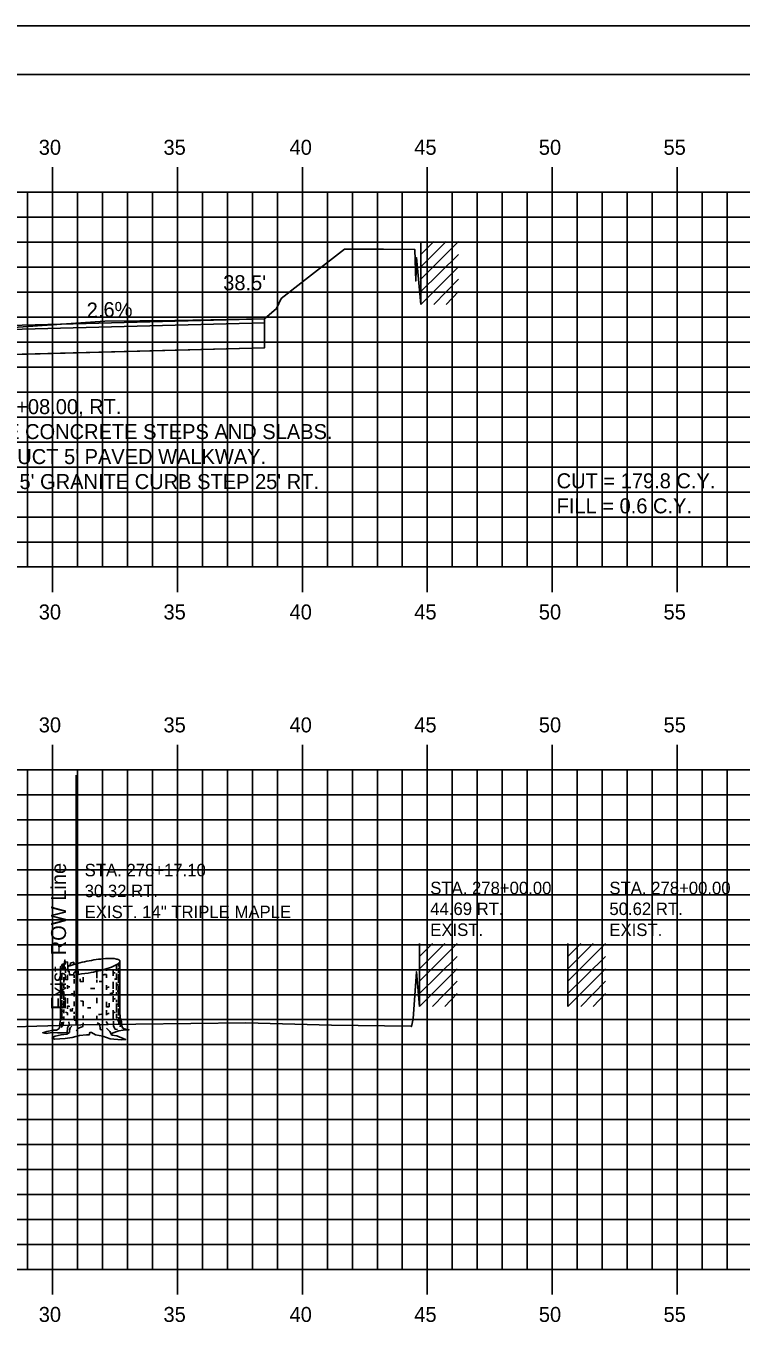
# Model space of a CAD drawing. Extents: x 854453 to 854623, y 366268 to 366378.
# Drawn here: x 854565.4 to 854594, y 366326.2 to 366378.2 of the extents above; entities that cross this region are included whole.
import ezdxf

# ---------------------------------------------------------------- set-up
doc = ezdxf.new("R2010")
doc.units = 0
for name, color, linetype in [('ANNOTATION', 7, 'Continuous'), ('BORDER', 7, 'Continuous'), ('D_Roadway_Sidewalks_Paved', 7, 'Continuous'), ('D_Roadway_SubGrade', 7, 'Continuous'), ('D_Text_Monospaced', 7, 'Continuous'), ('D_Text_Standard', 7, 'Continuous'), ('E_ROW_Line', 7, 'Continuous'), ('H_V ANNOTATION', 7, 'Continuous'), ('JUNK COM EXC', 7, 'Continuous'), ('MAJOR', 7, 'Continuous'), ('MINOR', 7, 'Continuous'), ('PLOT BOUNDARY', 7, 'Continuous'), ('S_Buildings', 7, 'Continuous'), ('S_Roadway_Centerline', 7, 'Continuous'), ('S_Trees_Decid_Pay', 7, 'Continuous')]:
    doc.layers.add(name, color=color, linetype=linetype)

msp = doc.modelspace()

# ---------------------------------------------------------------- linework, layer by layer
at = {"layer": 'BORDER'}
msp.add_line((854621.439, 366376.236), (854461.439, 366376.236), dxfattribs=at)
at = {"layer": 'D_Roadway_Sidewalks_Paved'}
for p, q in [((854561.855, 366366.118), (854574.919, 366366.457)), ((854561.855, 366365.951), (854574.919, 366366.291))]:
    msp.add_line(p, q, dxfattribs=at)
at = {"layer": 'D_Roadway_SubGrade'}
for p in [(854574.919, 366366.457), (854562.439, 366364.966)]:
    msp.add_line(p, (854574.919, 366365.29), dxfattribs=at)
at = {"layer": 'E_ROW_Line'}
msp.add_line((854567.378, 366338.192), (854567.378, 366348.192), dxfattribs=at)
at = {"layer": 'JUNK COM EXC'}
msp.add_lwpolyline([(854556.439, 366364.877), (854556.439, 366364.267), (854556.439, 366364.267), (854562.439, 366364.387), (854562.439, 366364.966), (854574.919, 366365.29), (854574.919, 366366.457), (854571.334, 366366.391), (854568.525, 366366.364), (854564.488, 366366.083), (854560.855, 366365.814), (854560.601, 366365.825), (854560.033, 366365.848), (854558.145, 366365.029), (854557.7, 366364.856), (854556.439, 366364.877)], dxfattribs=at)
at = {"layer": 'MAJOR'}
for p, q in [((854566.439, 366372.523), (854566.439, 366371.521)), ((854571.439, 366372.523), (854571.439, 366371.521)), ((854576.439, 366372.523), (854576.439, 366371.521)), ((854581.439, 366372.523), (854581.439, 366371.521)), ((854586.439, 366372.523), (854586.439, 366371.521)), ((854591.439, 366372.523), (854591.439, 366371.521)), ((854466.439, 366371.521), (854606.439, 366371.521)), ((854566.439, 366356.521), (854566.439, 366371.521)), ((854571.439, 366356.521), (854571.439, 366371.521)), ((854576.439, 366356.521), (854576.439, 366371.521)), ((854581.439, 366356.521), (854581.439, 366371.521)), ((854586.439, 366356.521), (854586.439, 366371.521)), ((854591.439, 366356.521), (854591.439, 366371.521)), ((854466.439, 366366.521), (854606.439, 366366.521)), ((854466.439, 366361.521), (854606.439, 366361.521)), ((854466.439, 366356.521), (854606.439, 366356.521)), ((854466.439, 366356.521), (854606.439, 366356.521)), ((854566.439, 366355.519), (854566.439, 366356.521)), ((854571.439, 366355.519), (854571.439, 366356.521)), ((854576.439, 366355.519), (854576.439, 366356.521)), ((854581.439, 366355.519), (854581.439, 366356.521)), ((854586.439, 366355.519), (854586.439, 366356.521)), ((854591.439, 366355.519), (854591.439, 366356.521)), ((854566.439, 366349.403), (854566.439, 366348.401)), ((854571.439, 366349.403), (854571.439, 366348.401)), ((854576.439, 366349.403), (854576.439, 366348.401)), ((854581.439, 366349.403), (854581.439, 366348.401)), ((854586.439, 366349.403), (854586.439, 366348.401)), ((854591.439, 366349.403), (854591.439, 366348.401)), ((854466.439, 366348.401), (854606.439, 366348.401)), ((854466.439, 366348.401), (854606.439, 366348.401)), ((854566.439, 366328.401), (854566.439, 366348.401)), ((854571.439, 366328.401), (854571.439, 366348.401)), ((854576.439, 366328.401), (854576.439, 366348.401)), ((854581.439, 366328.401), (854581.439, 366348.401)), ((854586.439, 366328.401), (854586.439, 366348.401)), ((854591.439, 366328.401), (854591.439, 366348.401)), ((854466.439, 366343.401), (854606.439, 366343.401)), ((854466.439, 366338.401), (854606.439, 366338.401)), ((854466.439, 366333.401), (854606.439, 366333.401)), ((854466.439, 366328.401), (854606.439, 366328.401)), ((854466.439, 366328.401), (854606.439, 366328.401)), ((854566.439, 366327.399), (854566.439, 366328.401)), ((854571.439, 366327.399), (854571.439, 366328.401)), ((854576.439, 366327.399), (854576.439, 366328.401)), ((854581.439, 366327.399), (854581.439, 366328.401)), ((854586.439, 366327.399), (854586.439, 366328.401)), ((854591.439, 366327.399), (854591.439, 366328.401))]:
    msp.add_line(p, q, dxfattribs=at)
at = {"layer": 'MINOR'}
for p, q in [((854565.439, 366356.521), (854565.439, 366371.521)), ((854567.439, 366356.521), (854567.439, 366371.521)), ((854568.439, 366356.521), (854568.439, 366371.521)), ((854569.439, 366356.521), (854569.439, 366371.521)), ((854570.439, 366356.521), (854570.439, 366371.521)), ((854572.439, 366356.521), (854572.439, 366371.521)), ((854573.439, 366356.521), (854573.439, 366371.521)), ((854574.439, 366356.521), (854574.439, 366371.521)), ((854575.439, 366356.521), (854575.439, 366371.521)), ((854577.439, 366356.521), (854577.439, 366371.521)), ((854578.439, 366356.521), (854578.439, 366371.521)), ((854579.439, 366356.521), (854579.439, 366371.521)), ((854580.439, 366356.521), (854580.439, 366371.521)), ((854582.439, 366356.521), (854582.439, 366371.521)), ((854583.439, 366356.521), (854583.439, 366371.521)), ((854584.439, 366356.521), (854584.439, 366371.521)), ((854585.439, 366356.521), (854585.439, 366371.521)), ((854587.439, 366356.521), (854587.439, 366371.521)), ((854588.439, 366356.521), (854588.439, 366371.521)), ((854589.439, 366356.521), (854589.439, 366371.521)), ((854590.439, 366356.521), (854590.439, 366371.521)), ((854592.439, 366356.521), (854592.439, 366371.521)), ((854593.439, 366356.521), (854593.439, 366371.521)), ((854466.439, 366370.521), (854606.439, 366370.521)), ((854466.439, 366369.521), (854606.439, 366369.521)), ((854466.439, 366368.521), (854606.439, 366368.521)), ((854466.439, 366367.521), (854606.439, 366367.521)), ((854466.439, 366365.521), (854606.439, 366365.521)), ((854466.439, 366364.521), (854606.439, 366364.521)), ((854466.439, 366363.521), (854606.439, 366363.521)), ((854466.439, 366362.521), (854606.439, 366362.521)), ((854466.439, 366360.521), (854606.439, 366360.521)), ((854466.439, 366359.521), (854606.439, 366359.521)), ((854466.439, 366358.521), (854606.439, 366358.521)), ((854466.439, 366357.521), (854606.439, 366357.521)), ((854565.439, 366328.401), (854565.439, 366348.401)), ((854567.439, 366328.401), (854567.439, 366348.401)), ((854568.439, 366328.401), (854568.439, 366348.401)), ((854569.439, 366328.401), (854569.439, 366348.401)), ((854570.439, 366328.401), (854570.439, 366348.401)), ((854572.439, 366328.401), (854572.439, 366348.401)), ((854573.439, 366328.401), (854573.439, 366348.401)), ((854574.439, 366328.401), (854574.439, 366348.401)), ((854575.439, 366328.401), (854575.439, 366348.401)), ((854577.439, 366328.401), (854577.439, 366348.401)), ((854578.439, 366328.401), (854578.439, 366348.401)), ((854579.439, 366328.401), (854579.439, 366348.401)), ((854580.439, 366328.401), (854580.439, 366348.401)), ((854582.439, 366328.401), (854582.439, 366348.401)), ((854583.439, 366328.401), (854583.439, 366348.401)), ((854584.439, 366328.401), (854584.439, 366348.401)), ((854585.439, 366328.401), (854585.439, 366348.401)), ((854587.439, 366328.401), (854587.439, 366348.401)), ((854588.439, 366328.401), (854588.439, 366348.401)), ((854589.439, 366328.401), (854589.439, 366348.401)), ((854590.439, 366328.401), (854590.439, 366348.401)), ((854592.439, 366328.401), (854592.439, 366348.401)), ((854593.439, 366328.401), (854593.439, 366348.401)), ((854466.439, 366347.401), (854606.439, 366347.401)), ((854466.439, 366346.401), (854606.439, 366346.401)), ((854466.439, 366345.401), (854606.439, 366345.401)), ((854466.439, 366344.401), (854606.439, 366344.401)), ((854466.439, 366342.401), (854606.439, 366342.401)), ((854466.439, 366341.401), (854606.439, 366341.401)), ((854466.439, 366340.401), (854606.439, 366340.401)), ((854466.439, 366339.401), (854606.439, 366339.401)), ((854466.439, 366337.401), (854606.439, 366337.401)), ((854466.439, 366336.401), (854606.439, 366336.401)), ((854466.439, 366335.401), (854606.439, 366335.401)), ((854466.439, 366334.401), (854606.439, 366334.401)), ((854466.439, 366332.401), (854606.439, 366332.401)), ((854466.439, 366331.401), (854606.439, 366331.401)), ((854466.439, 366330.401), (854606.439, 366330.401)), ((854466.439, 366329.401), (854606.439, 366329.401))]:
    msp.add_line(p, q, dxfattribs=at)
at = {"layer": 'PLOT BOUNDARY'}
msp.add_lwpolyline([(854453.345, 366268.177), (854623.345, 366268.177), (854623.345, 366378.177), (854453.345, 366378.177)], close=True, dxfattribs=at)
at = {"layer": 'S_Buildings'}
for p, q in [((854581.178, 366367.023), (854581.178, 366369.549)), ((854581.178, 366368.04), (854582.687, 366369.549)), ((854581.178, 366368.532), (854582.195, 366369.549)), ((854581.178, 366369.024), (854581.703, 366369.549)), ((854581.178, 366367.548), (854582.687, 366369.024)), ((854581.178, 366367.023), (854582.687, 366368.532)), ((854581.703, 366367.023), (854582.687, 366368.04)), ((854582.195, 366367.023), (854582.687, 366367.548)), ((854581.128, 366338.925), (854581.128, 366341.451)), ((854581.128, 366339.942), (854582.638, 366341.451)), ((854581.128, 366340.434), (854582.145, 366341.451)), ((854581.128, 366340.927), (854581.653, 366341.451)), ((854587.061, 366338.924), (854587.061, 366341.451)), ((854587.061, 366339.941), (854588.57, 366341.451)), ((854587.061, 366340.434), (854588.078, 366341.451)), ((854587.061, 366340.926), (854587.586, 366341.451)), ((854581.128, 366339.45), (854582.638, 366340.927)), ((854587.061, 366339.449), (854588.57, 366340.926)), ((854581.128, 366338.925), (854582.638, 366340.434)), ((854581.653, 366338.925), (854582.638, 366339.942)), ((854587.061, 366338.924), (854588.57, 366340.434)), ((854587.586, 366338.924), (854588.57, 366339.941)), ((854582.145, 366338.925), (854582.638, 366339.45)), ((854588.078, 366338.924), (854588.57, 366339.449))]:
    msp.add_line(p, q, dxfattribs=at)
at = {"layer": 'S_Roadway_Centerline'}
for points in [[(854564.488, 366366.083), (854568.525, 366366.364), (854571.334, 366366.391), (854574.919, 366366.457), (854575.406, 366366.873), (854575.586, 366367.263), (854576.808, 366368.22), (854578.128, 366369.249), (854579.68, 366369.245), (854580.939, 366369.236), (854580.973, 366367.966), (854581.007, 366368.905), (854581.178, 366367.023)], [(854563.145, 366338.061), (854567.572, 366338.198), (854574.173, 366338.276), (854577.605, 366338.183), (854580.792, 366338.137), (854580.801, 366338.123), (854580.869, 366338.44), (854581.002, 366340.319), (854581.128, 366338.926)]]:
    msp.add_lwpolyline(points, dxfattribs=at)
at = {"layer": 'S_Trees_Decid_Pay'}
for p, q in [((854566.955, 366340.446), (854566.955, 366340.272)), ((854568.999, 366340.605), (854568.999, 366340.352)), ((854569.079, 366340.649), (854569.079, 366340.529)), ((854569.079, 366340.477), (854569.079, 366340.263)), ((854566.805, 366340.246), (854566.805, 366339.991)), ((854566.891, 366340.1), (854566.891, 366339.888)), ((854567.039, 366340.197), (854567.039, 366339.993)), ((854567.3, 366340.199), (854567.3, 366340.08)), ((854567.3, 366340.028), (854567.3, 366339.843)), ((854567.539, 366339.928), (854567.544, 366340.035)), ((854567.665, 366340.1), (854567.665, 366339.92)), ((854568.211, 366340.337), (854568.211, 366340.057)), ((854568.211, 366339.991), (854568.211, 366339.888)), ((854568.594, 366340.438), (854568.594, 366340.352)), ((854568.594, 366340.211), (854568.594, 366340.071)), ((854568.867, 366340.352), (854568.867, 366340.16)), ((854568.999, 366340.255), (854568.999, 366339.991)), ((854569.079, 366340.218), (854569.079, 366339.88)), ((854566.805, 366339.894), (854566.805, 366339.425)), ((854566.891, 366339.823), (854566.891, 366339.674)), ((854566.891, 366339.497), (854566.891, 366339.197)), ((854567.039, 366339.785), (854567.039, 366339.631)), ((854567.3, 366339.557), (854567.3, 366339.329)), ((854568.594, 366339.785), (854568.594, 366339.594)), ((854568.867, 366339.909), (854568.867, 366339.631)), ((854568.867, 366339.586), (854568.867, 366339.477)), ((854568.999, 366339.894), (854568.999, 366339.586)), ((854568.999, 366339.497), (854568.999, 366339.431)), ((854569.079, 366339.763), (854569.079, 366339.402)), ((854566.805, 366339.374), (854566.805, 366339.24)), ((854566.805, 366339.182), (854566.805, 366338.857)), ((854566.891, 366339.159), (854566.891, 366338.917)), ((854567.039, 366339.268), (854567.039, 366339.048)), ((854567.039, 366338.949), (854567.039, 366338.828)), ((854567.3, 366339.13), (854567.3, 366338.945)), ((854567.665, 366339.142), (854567.665, 366338.945)), ((854568.211, 366339.277), (854568.211, 366339.056)), ((854568.594, 366339.114), (854568.594, 366338.906)), ((854568.867, 366339.342), (854568.867, 366339.114)), ((854568.999, 366339.197), (854568.999, 366339.1)), ((854568.999, 366339.048), (854568.999, 366338.688)), ((854569.079, 366339.365), (854569.079, 366338.917)), ((854566.805, 366338.828), (854566.805, 366338.408)), ((854566.891, 366338.806), (854566.891, 366338.665)), ((854566.891, 366338.533), (854566.891, 366338.377)), ((854567.039, 366338.677), (854567.039, 366338.579)), ((854567.3, 366338.711), (854567.3, 366338.634)), ((854567.3, 366338.556), (854567.3, 366338.383)), ((854567.665, 366338.562), (854567.665, 366338.459)), ((854568.211, 366338.556), (854568.211, 366338.383)), ((854568.594, 366338.785), (854568.594, 366338.585)), ((854568.867, 366338.785), (854568.867, 366338.401)), ((854568.999, 366338.636), (854568.999, 366338.47)), ((854569.079, 366338.851), (854569.079, 366338.569)), ((854566.808, 366338.305), (854566.794, 366338.188)), ((854568.59, 366338.328), (854568.67, 366338.196))]:
    msp.add_line(p, q, dxfattribs=at)
for points in [[(854566.755, 366340.52), (854566.755, 366338.383), (854566.734, 366338.241), (854566.728, 366338.115), (854566.685, 366338.029), (854566.592, 366337.98), (854566.457, 366337.98), (854566.213, 366337.924), (854566.047, 366337.875), (854566.189, 366337.844), (854566.426, 366337.881), (854566.636, 366337.869), (854566.897, 366337.875), (854567.021, 366337.893), (854567.051, 366337.85), (854567.113, 366337.893), (854567.014, 366337.825), (854566.779, 366337.8), (854566.549, 366337.739), (854566.419, 366337.669), (854566.518, 366337.625), (854566.94, 366337.644), (854567.218, 366337.688), (854567.517, 366337.764), (854567.803, 366337.8), (854567.908, 366337.8), (854567.926, 366337.881), (854567.995, 366337.887), (854568.161, 366337.8), (854568.447, 366337.745), (854568.746, 366337.638), (854569.205, 366337.588), (854569.36, 366337.601), (854569.018, 366337.751), (854568.814, 366337.782), (854568.826, 366337.856), (854569.086, 366337.955), (854569.261, 366337.986), (854569.502, 366337.998), (854569.304, 366338.035), (854569.242, 366338.072), (854569.218, 366338.159), (854569.205, 366338.328), (854569.16, 366338.414), (854569.132, 366338.655), (854569.132, 366340.741)], [(854567.111, 366340.193), (854567.103, 366340.337), (854567.058, 366340.329), (854567.043, 366340.704), (854566.949, 366340.712), (854566.934, 366340.792), (854566.897, 366340.455), (854566.852, 366340.549), (854566.831, 366340.395), (854566.755, 366340.52), (854566.76, 366340.331)], [(854566.755, 366340.52), (854566.8, 366340.543), (854566.823, 366340.609), (854566.875, 366340.632), (854566.908, 366340.557)], [(854567.133, 366340.559), (854567.154, 366340.667), (854567.286, 366340.697), (854567.293, 366340.609)], [(854567.272, 366340.197), (854567.309, 366340.3), (854567.375, 366340.306), (854567.375, 366340.388), (854567.449, 366340.395), (854567.474, 366340.214)], [(854568.708, 366338.92), (854568.707, 366338.997), (854568.699, 366339.063)], [(854567.163, 366338.828), (854567.154, 366338.754), (854567.228, 366338.748), (854567.243, 366338.865)], [(854569.024, 366338.416), (854569.096, 366338.313), (854569.096, 366338.188)], [(854569.081, 366338.497), (854569.142, 366338.336), (854569.155, 366338.211), (854569.148, 366338.113)], [(854566.875, 366338.313), (854566.868, 366338.188), (854566.786, 366338.093)], [(854567.021, 366337.893), (854567.039, 366338.072), (854567.101, 366338.209), (854567.094, 366338.309)], [(854567.212, 366338.14), (854567.138, 366338.072), (854567.119, 366337.974), (854567.113, 366337.893)], [(854567.663, 366338.276), (854567.646, 366338.122), (854567.449, 366338.041), (854567.403, 366337.938)], [(854568.229, 366338.268), (854568.332, 366338.216), (854568.346, 366338.01), (854568.449, 366337.982)], [(854568.814, 366337.782), (854568.728, 366337.924), (854568.596, 366338.066)], [(854568.884, 366338.342), (854568.884, 366338.136), (854568.942, 366338.027), (854569.039, 366338.01)]]:
    msp.add_lwpolyline(points, dxfattribs=at)
for centre, radius, start, end in [((854567.564, 366339.333), 1.299, 107.8613, 113.3069), ((854569.045, 366334.739), 6.126, 100.7779, 107.8613), ((854569.045, 366334.739), 6.126, 93.6944, 100.7779), ((854566.842, 366346.308), 6.126, 280.7779, 287.8613), ((854568.734, 366339.556), 1.299, 78.2779, 93.6944), ((854568.323, 366341.714), 1.299, 287.8613, 303.2779), ((854568.9, 366340.358), 0.48, 69.9843, 78.2779), ((854568.772, 366341.029), 0.48, 303.2779, 311.5714), ((854569.008, 366340.655), 0.164, 55.7779, 69.9843), ((854568.982, 366340.793), 0.164, 311.5714, 325.7779), ((854569.04, 366340.702), 0.107, 45.9547, 55.7779), ((854569.07, 366340.732), 0.0645, 33.2779, 45.9547), ((854569.029, 366340.761), 0.107, 325.7779, 335.6011), ((854569.078, 366340.738), 0.0544, 22.46, 33.2779), ((854569.068, 366340.743), 0.0645, 335.6011, 348.2779), ((854569.085, 366340.741), 0.0467, 10.7779, 22.46), ((854569.085, 366340.741), 0.0467, 359.0957, 10.7779), ((854569.078, 366340.741), 0.0544, 348.2779, 359.0957), ((854566.802, 366340.152), 0.0476, 180, 191.6815), ((854566.81, 366340.153), 0.0554, 191.6815, 202.5), ((854566.82, 366340.157), 0.0657, 202.5, 215.1737), ((854566.855, 366340.182), 0.109, 215.1737, 225), ((854566.896, 366340.223), 0.166, 225, 239.1924), ((854567.368, 366341.242), 1.292, 250.6119, 255.2856), ((854567.153, 366341.492), 1.299, 268.1289, 273.6944), ((854566.842, 366346.308), 6.126, 273.6944, 274.0246), ((854566.842, 366346.308), 6.126, 275.9147, 280.7779), ((854567.943, 366345.83), 5.916, 266.0776, 267.3043), ((854567.943, 366345.83), 5.916, 273.5382, 274.8924), ((854567.944, 366346.091), 5.916, 274.9515, 276.3087), ((854568.52, 366341.503), 1.292, 285.5651, 289.0916), ((854568.519, 366341.242), 1.292, 288.0829, 292.5), ((854568.828, 366340.496), 0.484, 297.4162, 300.8076), ((854568.991, 366340.223), 0.166, 300.8076, 315), ((854568.992, 366340.484), 0.166, 301.67, 315), ((854569.032, 366340.182), 0.109, 315, 324.8263), ((854569.033, 366340.443), 0.109, 315, 324.8263), ((854569.067, 366340.157), 0.0657, 324.8263, 337.5), ((854569.068, 366340.418), 0.0657, 324.8263, 337.5), ((854569.077, 366340.153), 0.0554, 337.5, 348.3185), ((854569.078, 366340.414), 0.0554, 337.5, 348.3185), ((854566.802, 366339.631), 0.0476, 180, 191.6815), ((854566.81, 366339.633), 0.0554, 191.6815, 202.5), ((854566.82, 366339.636), 0.0657, 202.5, 215.1737), ((854566.855, 366339.661), 0.109, 215.1737, 225), ((854566.896, 366339.702), 0.166, 225, 239.1924), ((854566.896, 366339.959), 0.166, 237.0378, 239.1924), ((854567.058, 366340.232), 0.484, 239.1924, 247.5), ((854567.058, 366339.975), 0.484, 239.1924, 245.7725), ((854567.368, 366340.979), 1.292, 247.5, 248.3537), ((854567.368, 366340.721), 1.292, 247.5, 248.4842), ((854567.368, 366340.979), 1.292, 255.2856, 259.2632), ((854567.368, 366340.721), 1.292, 261.8726, 262.8454), ((854567.943, 366345.309), 5.916, 262.8454, 263.7595), ((854567.943, 366345.567), 5.916, 270.1162, 271.7708), ((854567.943, 366345.567), 5.916, 276.3184, 277.1546), ((854568.519, 366340.979), 1.292, 277.1546, 278.3662), ((854568.519, 366340.721), 1.292, 279.2565, 285.6105), ((854568.519, 366340.979), 1.292, 291.8071, 292.5), ((854568.828, 366340.232), 0.484, 292.5, 300.8076), ((854568.828, 366339.975), 0.484, 294.6372, 300.8076), ((854568.991, 366339.959), 0.166, 300.8076, 301.6001), ((854568.991, 366339.702), 0.166, 300.8076, 315), ((854569.032, 366339.661), 0.109, 315, 324.8263), ((854569.067, 366339.636), 0.0657, 324.8263, 337.5), ((854569.077, 366339.633), 0.0554, 337.5, 348.3185), ((854566.802, 366339.374), 0.0476, 180, 191.6815), ((854566.802, 366339.108), 0.0476, 180, 191.6815), ((854566.81, 366339.375), 0.0554, 191.6815, 202.5), ((854566.81, 366339.11), 0.0554, 191.6815, 202.5), ((854566.82, 366339.379), 0.0657, 202.5, 215.1737), ((854566.82, 366339.113), 0.0657, 202.5, 215.1737), ((854566.855, 366339.404), 0.109, 215.1737, 225), ((854566.855, 366339.138), 0.109, 215.1737, 225), ((854566.896, 366339.445), 0.166, 225, 239.1924), ((854566.896, 366339.179), 0.166, 225, 239.1924), ((854567.058, 366339.452), 0.484, 239.1924, 247.5), ((854567.368, 366340.464), 1.292, 247.5, 251.799), ((854567.368, 366340.198), 1.292, 247.5, 248.3537), ((854567.368, 366340.198), 1.292, 255.2856, 259.2463), ((854567.943, 366345.052), 5.916, 266.2721, 267.3043), ((854567.943, 366344.786), 5.916, 276.3184, 277.1546), ((854568.519, 366340.198), 1.292, 277.1546, 278.3795), ((854568.519, 366340.464), 1.292, 285.6105, 290.1001), ((854568.828, 366339.452), 0.484, 292.5, 300.8076), ((854568.991, 366339.179), 0.166, 300.8076, 302.0694), ((854568.991, 366339.445), 0.166, 302.0694, 315), ((854569.032, 366339.404), 0.109, 315, 324.8263), ((854569.067, 366339.379), 0.0657, 324.8263, 337.5), ((854569.077, 366339.375), 0.0554, 337.5, 348.3185), ((854569.077, 366339.11), 0.0554, 337.5, 348.3185), ((854566.802, 366338.579), 0.0476, 180, 191.6815), ((854566.81, 366338.58), 0.0554, 191.6815, 202.5), ((854566.82, 366338.584), 0.0657, 202.5, 215.1737), ((854566.855, 366338.609), 0.109, 215.1737, 225), ((854566.896, 366338.65), 0.166, 225, 239.1924), ((854567.058, 366338.923), 0.484, 239.1924, 247.5), ((854567.058, 366339.18), 0.484, 242.734, 247.5), ((854567.368, 366339.669), 1.292, 247.5, 248.3537), ((854567.368, 366339.927), 1.292, 251.3664, 255.2856), ((854567.943, 366344.257), 5.916, 263.7831, 264.7656), ((854567.943, 366344.786), 5.916, 268.9207, 270), ((854567.943, 366344.786), 5.916, 270, 270.2757), ((854567.943, 366344.514), 5.916, 273.2637, 274.461), ((854567.943, 366344.514), 5.916, 276.3184, 277.1546), ((854568.519, 366339.927), 1.292, 277.1546, 278.3662), ((854568.519, 366339.927), 1.292, 285.6105, 289.1534), ((854568.528, 366339.673), 1.292, 291.3696, 292.0604), ((854568.828, 366338.923), 0.484, 292.5, 296.5499), ((854568.991, 366338.907), 0.166, 302.0694, 315), ((854569.032, 366338.867), 0.109, 315, 324.8263), ((854569.067, 366338.842), 0.0657, 324.8263, 337.5), ((854569.077, 366338.838), 0.0554, 337.5, 348.3185)]:
    msp.add_arc(centre, radius, start, end, dxfattribs=at)

# ---------------------------------------------------------------- texts
at = {"layer": 'ANNOTATION'}
msp.add_text('2.6%', height=0.6, rotation=1.4887, dxfattribs=at).set_placement((854567.815, 366366.501))
for s, p in [('STA. 278+08.00, RT.', (854561.639, 366362.641)), ('REMOVE CONCRETE STEPS AND SLABS.', (854561.639, 366361.641)), ("CONSTRUCT 5' PAVED WALKWAY.", (854561.639, 366360.641)), ("INSTALL 5' GRANITE CURB STEP 25' RT.", (854561.639, 366359.641)), ('CUT = 179.8 C.Y.', (854586.615, 366359.671)), ('FILL = 0.6 C.Y.', (854586.615, 366358.669))]:
    msp.add_text(s, height=0.6, dxfattribs=at).set_placement(p)
at = {"layer": 'D_Text_Monospaced'}
for s, height, p in [('STA. 278+17.10', 0.49998, (854567.724, 366344.139)), ('30.32 RT.', 0.5, (854567.724, 366343.305)), ('STA. 278+00.00', 0.49998, (854581.556, 366343.424)), ('STA. 278+00.00', 0.49998, (854588.727, 366343.423)), ('44.69 RT.', 0.5, (854581.556, 366342.59)), ('50.62 RT.', 0.5, (854588.727, 366342.589)), ('EXIST. 14" TRIPLE MAPLE', 0.49998, (854567.724, 366342.465)), ('EXIST. ', 0.5, (854581.556, 366341.75)), ('EXIST. ', 0.5, (854588.727, 366341.749))]:
    msp.add_text(s, height=height, dxfattribs=at).set_placement(p)
at = {"layer": 'D_Text_Standard'}
msp.add_text("38.5'", height=0.6, dxfattribs=at).set_placement((854573.27, 366367.601))
at = {"layer": 'E_ROW_Line'}
msp.add_text('Exist. ROW Line', height=0.6, rotation=90, dxfattribs=at).set_placement((854566.978, 366338.792))
at = {"layer": 'H_V ANNOTATION'}
for s, p in [('30', (854565.887, 366373.021)), ('35', (854570.879, 366373.021)), ('40', (854575.925, 366373.021)), ('45', (854580.917, 366373.021)), ('50', (854585.903, 366373.021)), ('55', (854590.895, 366373.021)), ('30', (854565.887, 366354.421)), ('35', (854570.879, 366354.421)), ('40', (854575.925, 366354.421)), ('45', (854580.917, 366354.421)), ('50', (854585.903, 366354.421)), ('55', (854590.895, 366354.421)), ('30', (854565.887, 366349.901)), ('35', (854570.879, 366349.901)), ('40', (854575.925, 366349.901)), ('45', (854580.917, 366349.901)), ('50', (854585.903, 366349.901)), ('55', (854590.895, 366349.901)), ('30', (854565.887, 366326.301)), ('35', (854570.879, 366326.301)), ('40', (854575.925, 366326.301)), ('45', (854580.917, 366326.301)), ('50', (854585.903, 366326.301)), ('55', (854590.895, 366326.301))]:
    msp.add_text(s, height=0.6, dxfattribs=at).set_placement(p)

doc.saveas('drawing.dxf')
